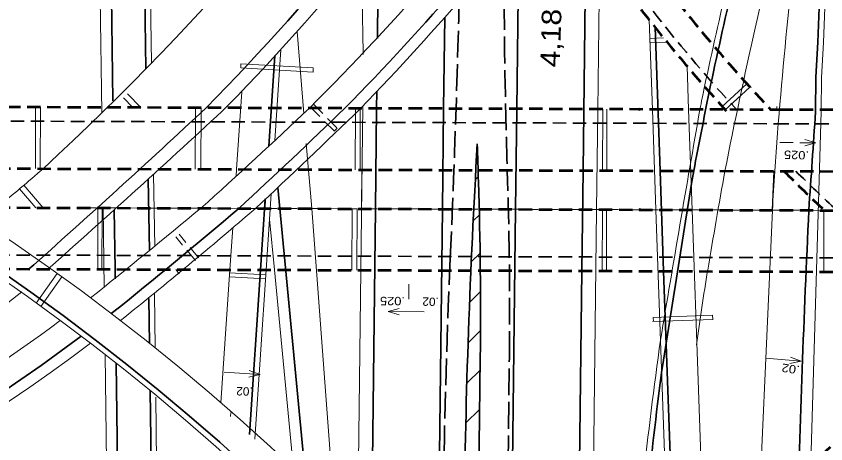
# Model space of a CAD drawing. Extents: x 2354993 to 2372084, y 6966390 to 6990057.
# Drawn here: x 2364175 to 2364756, y 6977811 to 6978118 of the extents above; entities that cross this region are included whole.
import ezdxf

# ---------------------------------------------------------------- set-up
doc = ezdxf.new("R2010")
doc.units = 0
doc.header["$LTSCALE"] = 3.2
doc.header["$PDMODE"] = 32
doc.header["$PDSIZE"] = 1.6
doc.linetypes.add('LONG_DASHED', pattern=[7.5, 6, -1.5])
doc.linetypes.add('MEDIUM_DASHED', pattern=[4.5, 3, -1.5])
for name, color, linetype, lineweight in [('11', 7, 'Continuous', 13), ('12', 7, 'Continuous', 13), ('13', 7, 'Continuous', 13), ('17', 7, 'Continuous', 13), ('19', 7, 'Continuous', 13), ('2', 7, 'Continuous', 35), ('4', 7, 'Continuous', 13), ('5', 7, 'Continuous', 35), ('6', 7, 'Continuous', 35), ('61', 7, 'Continuous', 13), ('9', 7, 'Continuous', 13)]:
    doc.layers.add(name, color=color, linetype=linetype, lineweight=lineweight)

msp = doc.modelspace()

# ---------------------------------------------------------------- linework, layer by layer
at = {"layer": '12'}
for p, q in [((2364639.282, 6978102.068), (2364629.368, 6978101.717)), ((2364629.474, 6978098.719), (2364629.368, 6978101.717)), ((2364641.658, 6978099.149), (2364629.474, 6978098.719)), ((2364336.085, 6978083.534), (2364335.918, 6978080.539)), ((2364387.788, 6978077.625), (2364335.918, 6978080.539)), ((2364387.955, 6978080.62), (2364336.085, 6978083.534)), ((2364387.955, 6978080.62), (2364387.788, 6978077.625)), ((2364254.643, 6978061.986), (2364264.214, 6978052.09)), ((2364251.767, 6978059.206), (2364258.631, 6978052.109)), ((2364303.49, 6978051.956), (2364303.342, 6978007.956)), ((2364307.49, 6978051.943), (2364307.342, 6978007.943)), ((2364595.638, 6978050.972), (2364595.489, 6978006.971)), ((2364598.637, 6978050.962), (2364598.489, 6978006.96)), ((2364405.149, 6978037.355), (2364403.014, 6978035.247)), ((2364632.9, 6978001.779), (2364633.006, 6977998.781)), ((2364177.285, 6977993.799), (2364188.905, 6977980.343)), ((2364180.313, 6977996.413), (2364194.206, 6977980.325)), ((2364233.491, 6977980.194), (2364233.343, 6977936.195)), ((2364236.49, 6977980.184), (2364236.343, 6977936.184)), ((2364595.395, 6977978.973), (2364595.246, 6977934.974)), ((2364598.394, 6977978.963), (2364598.246, 6977934.964)), ((2364754.238, 6977978.438), (2364754.09, 6977934.439)), ((2364291.836, 6977932.899), (2364289.272, 6977936.004)), ((2364294.92, 6977935.445), (2364294.473, 6977935.986)), ((2364353.954, 6977932.293), (2364327.993, 6977933.752)), ((2364353.755, 6977929.299), (2364327.795, 6977930.758)), ((2364636.538, 6977898.843), (2364636.432, 6977901.841)), ((2364328.77, 6977833.551), (2364328.601, 6977830.555))]:
    msp.add_line(p, q, dxfattribs=at)
at = {"layer": '17'}
for p, q in [((2364204.365, 6977933.072), (2364189.184, 6977911.942)), ((2364207.613, 6977930.738), (2364192.433, 6977909.608))]:
    msp.add_line(p, q, dxfattribs=at)
at = {"layer": '19', "linetype": 'MEDIUM_DASHED'}
msp.add_line((2364748.458, 6978026.804), (2364740.431, 6978024.644), dxfattribs=at)
at = {"layer": '19'}
for p, q in [((2364456.571, 6977925.613), (2364456.532, 6977914.768)), ((2364441.679, 6977905.795), (2364449.687, 6977908.023)), ((2364737.958, 6977870.263), (2364729.803, 6977868.66)), ((2364349.779, 6977860.687), (2364341.654, 6977858.935))]:
    msp.add_line(p, q, dxfattribs=at)
at = {"layer": '19', "linetype": 'MEDIUM_DASHED'}
msp.add_lwpolyline([(2364722.677, 6978027.18), (2364748.458, 6978026.804), (2364740.503, 6978029.196)], dxfattribs=at)
at = {"layer": '19'}
for points in [[(2364467.461, 6977905.634), (2364441.679, 6977905.795), (2364449.653, 6977903.47)], [(2364712.265, 6977872.416), (2364737.958, 6977870.263), (2364730.188, 6977873.197)], [(2364324.051, 6977862.367), (2364349.779, 6977860.687), (2364341.956, 6977863.478)]]:
    msp.add_lwpolyline(points, dxfattribs=at)
at = {"layer": '2'}
for p, q in [((2364535.5, 6978179.675), (2364533.978, 6978050.938)), ((2364581.463, 6978007.018), (2364583.464, 6978176.442)), ((2364481.479, 6978051.356), (2364482.253, 6978116.922)), ((2364360.38, 6978089.14), (2364356.077, 6978024.467)), ((2364533.131, 6977979.184), (2364533.978, 6978050.938)), ((2364580.614, 6977935.024), (2364581.463, 6978007.018)), ((2364353.542, 6977986.36), (2364350.178, 6977935.801)), ((2364353.105, 6977979.791), (2364353.566, 6977986.724)), ((2364529.276, 6977652.647), (2364533.131, 6977979.184)), ((2364342.329, 6977817.816), (2364350.178, 6977935.801)), ((2364576.847, 6977615.806), (2364580.614, 6977935.024))]:
    msp.add_line(p, q, dxfattribs=at)
at = {"layer": '4'}
for p, q in [((2364591.974, 6978050.253), (2364593.298, 6978162.457)), ((2364591.132, 6977978.904), (2364591.974, 6978050.253))]:
    msp.add_line(p, q, dxfattribs=at)
msp.add_lwpolyline([(2364586.065, 6977549.629), (2364586.993, 6977628.202), (2364591.132, 6977978.904)], dxfattribs=at)
at = {"layer": '4', "lineweight": 35}
for centre, radius, start, end in [((2447731.961, 6972326.416), 83180.808, 176.05509, 176.1038), ((2376431.6, 6977432.787), 11700.93, 177.32697, 178.44412)]:
    msp.add_arc(centre, radius, start, end, dxfattribs=at)
at = {"layer": '5'}
for p, q in [((2364267.888, 6978079.876), (2364263.771, 6978392.69)), ((2364433.986, 6978101.712), (2364434.867, 6978175.192)), ((2364433.997, 6978102.679), (2364433.986, 6978101.712)), ((2364433.384, 6978051.518), (2364433.533, 6978063.932)), ((2364270.487, 6977949.705), (2364269.459, 6978000.752)), ((2364504.339, 6978000.478), (2364506.337, 6978002.43)), ((2364502.851, 6977971.069), (2364506.967, 6977975.089)), ((2364501.363, 6977941.66), (2364507.57, 6977947.722)), ((2364245.809, 6977936.153), (2364245.898, 6977929.366)), ((2364648.972, 6977660.539), (2364639.273, 6977934.826)), ((2364500.194, 6977912.562), (2364507.73, 6977919.922)), ((2364270.48, 6977882.999), (2364270.055, 6977915.309)), ((2364499.216, 6977883.65), (2364507.731, 6977891.966)), ((2364246.695, 6977868.679), (2364257.91, 6977015.279)), ((2364498.238, 6977854.739), (2364507.628, 6977863.909)), ((2364280.781, 6977100.108), (2364270.924, 6977849.204)), ((2364497.402, 6977825.967), (2364507.294, 6977835.627))]:
    msp.add_line(p, q, dxfattribs=at)
at = {"layer": '5', "lineweight": 13}
for p, q in [((2364271.836, 6978083.919), (2364267.734, 6978395.661)), ((2364236.303, 6978048.324), (2364232.175, 6978361.911)), ((2364423.845, 6978091.472), (2364422.744, 6978138.5)), ((2364753.829, 6978098.812), (2364754.871, 6978123.787)), ((2364381.214, 6978047.774), (2364376.34, 6978106.754)), ((2364752.447, 6978073.796), (2364753.826, 6978098.758)), ((2364360.351, 6978028.437), (2364364.705, 6978093.867)), ((2364364.454, 6978090.1), (2364364.667, 6978093.308)), ((2364423.849, 6978090.291), (2364423.857, 6978090.987)), ((2364657.187, 6978050.764), (2364656.089, 6978081.807)), ((2364752.236, 6978048.996), (2364752.453, 6978073.982)), ((2364332.925, 6978007.856), (2364336.627, 6978063.503)), ((2364419.746, 6977748.182), (2364423.405, 6978053.282)), ((2364659.733, 6977978.756), (2364657.187, 6978050.764)), ((2364720.276, 6978050.551), (2364720.384, 6978053.024)), ((2364743.625, 6977758.845), (2364752.236, 6978048.996)), ((2364386.841, 6977979.677), (2364382.973, 6978026.488)), ((2364274.211, 6977952.737), (2364273.272, 6978004.224)), ((2364332.592, 6978002.852), (2364332.925, 6978007.856)), ((2364422.521, 6977979.556), (2364422.856, 6978007.553)), ((2364717.146, 6977978.563), (2364718.363, 6978006.556)), ((2364354.187, 6977935.787), (2364357.818, 6977990.359)), ((2364357.795, 6977990.008), (2364357.821, 6977990.399)), ((2364237.95, 6977923.17), (2364237.199, 6977980.181)), ((2364403.156, 6977764.879), (2364386.841, 6977979.677)), ((2364643.799, 6977693.64), (2364633.713, 6977978.844)), ((2364707.646, 6977760.094), (2364717.285, 6977978.562)), ((2364356.604, 6977972.114), (2364360.096, 6977935.765)), ((2364328.135, 6977935.875), (2364330.152, 6977966.192)), ((2364321.779, 6977840.341), (2364328.135, 6977935.875)), ((2364346.111, 6977814.399), (2364354.187, 6977935.787)), ((2364360.096, 6977935.765), (2364373.781, 6977793.307)), ((2364274.523, 6977879.763), (2364274.014, 6977918.463)), ((2364250.238, 6976989.323), (2364238.582, 6977875.031)), ((2364281.346, 6977361.167), (2364274.986, 6977844.567))]:
    msp.add_line(p, q, dxfattribs=at)
at = {"layer": '5', "linetype": 'MEDIUM_DASHED', "lineweight": 53}
for p, q in [((2364725.162, 6978050.535), (2364010.427, 6978052.946)), ((2365005.606, 6978049.588), (2364716.185, 6978050.564)), ((2364089.244, 6978008.678), (2364762.775, 6978006.406)), ((2363786.467, 6977981.699), (2365246.775, 6977976.776)), ((2363786.319, 6977937.7), (2365246.626, 6977932.776))]:
    msp.add_line(p, q, dxfattribs=at)
at = {"layer": '5', "linetype": 'MEDIUM_DASHED'}
for p, q in [((2364727.772, 6978040.524), (2364029.265, 6978042.88)), ((2365017.01, 6978039.548), (2364725.744, 6978040.53)), ((2363786.352, 6977947.7), (2365246.66, 6977942.776))]:
    msp.add_line(p, q, dxfattribs=at)
at = {"layer": '5', "linetype": 'MEDIUM_DASHED', "lineweight": 13}
msp.add_line((2364222.899, 6977980.23), (2364754.629, 6977978.436), dxfattribs=at)
at = {"layer": '5', "linetype": 'LONG_DASHED'}
msp.add_line((2364526.874, 6977725.884), (2364528.605, 6977872.51), dxfattribs=at)
at = {"layer": '5'}
for points in [[(2364748.237, 6978049.03), (2364748.453, 6978074.017), (2364749.833, 6978098.979), (2364750.875, 6978123.954), (2364753.046, 6978148.498), (2364754.481, 6978172.543), (2364756.316, 6978197.35), (2364758.434, 6978221.8), (2364760.985, 6978247.011), (2364763.785, 6978271.641), (2364766.943, 6978296.439), (2364770.374, 6978320.903), (2364774.178, 6978345.591), (2364778.407, 6978370.695), (2364796.946, 6978453.796)], [(2364639.273, 6977934.826), (2364636.727, 6978006.831), (2364633.086, 6978109.765)], [(2364429.624, 6977738.01), (2364432.519, 6977979.523), (2364433.384, 6978051.518)], [(2364477.172, 6977686.469), (2364480.63, 6977979.361), (2364481.479, 6978051.356)], [(2364496.142, 6977759.009), (2364495.756, 6977726.25), (2364506.002, 6977726.13), (2364507.732, 6977872.751)]]:
    msp.add_lwpolyline(points, dxfattribs=at)
at = {"layer": '5', "lineweight": 13}
for points in [[(2364633.713, 6977978.844), (2364631.167, 6978050.852), (2364628.897, 6978115.043)], [(2364680.862, 6977352.125), (2364668.863, 6977720.558), (2364659.733, 6977978.756)]]:
    msp.add_lwpolyline(points, dxfattribs=at)
at = {"layer": '5', "linetype": 'MEDIUM_DASHED', "lineweight": 53}
for centre, radius, start, end in [((2365591.415, 6978874.774), 1226.227, 157.96139, 222.27477), ((2365591.415, 6978874.774), 1202.227, 157.96139, 223.28034), ((2365591.415, 6978874.774), 1226.227, 225.07731, 226.96804), ((2365952.337, 6976500.333), 1770.947, 128.18302, 142.02993), ((2365952.338, 6976500.332), 1744.947, 127.94306, 142.26149)]:
    msp.add_arc(centre, radius, start, end, dxfattribs=at)
at = {"layer": '5', "linetype": 'MEDIUM_DASHED'}
for centre, radius, start, end in [((2365591.415, 6978874.774), 1220.227, 157.96139, 222.48424), ((2365591.415, 6978874.774), 1220.227, 225.36243, 227.27274), ((2365952.338, 6976500.332), 1748.947, 127.98178, 142.22456)]:
    msp.add_arc(centre, radius, start, end, dxfattribs=at)
at = {"layer": '5', "lineweight": 13}
for centre, radius, start, end in [((2362823.255, 6979494.499), 2021.91, 312.68984, 326.1095), ((2363008.703, 6979329.968), 1834.853, 315.90902, 326.07506), ((2363083.622, 6979356.349), 1842.854, 314.93085, 323.30202), ((2363244.672, 6976597.082), 1645.014, 38.12295, 103.3303), ((2363062.003, 6979373.816), 1896.709, 315.80261, 322.95759), ((2368298.716, 6977752.87), 3588.778, 172.43843, 175.94649), ((2363244.672, 6976597.082), 1619.014, 38.12295, 103.3303), ((2368172.363, 6977322.346), 3582.03, 165.52996, 167.99765), ((2368799.967, 6977188.312), 4197.305, 165.90092, 168.75683), ((2367491.502, 6977482.494), 2882.789, 168.29699, 168.63166), ((2359454.929, 6983291.9), 7153.737, 311.52024, 312.92114), ((2361503.345, 6981100.379), 4195.154, 311.94226, 313.38798), ((2361441.841, 6981104.619), 4266.326, 312.90909, 314.30611), ((2381410.768, 6975102.784), 17003, 170.0157, 170.58074), ((2363127.192, 6979233.99), 1625.022, 309.51957, 311.04051), ((2371644.782, 6976761.528), 7072.044, 169.8593, 170.44507), ((2367582.002, 6977825.766), 2868.789, 176.38689, 176.9469), ((2361053.508, 6981904.182), 5097.73, 308.51788, 309.66398), ((2361981.19, 6980728.955), 3626.643, 308.71864, 310.70824), ((2367491.502, 6977482.494), 2856.789, 170.87724, 171.96261), ((2363127.192, 6979233.99), 1683.022, 290.12282, 308.67239), ((2363217.727, 6979240.251), 1666, 287.12386, 306.40449), ((2363217.727, 6979240.251), 1692, 268.21361, 306.66787), ((2367491.502, 6977482.494), 2882.789, 171.96478, 176.02877)]:
    msp.add_arc(centre, radius, start, end, dxfattribs=at)
at = {"layer": '5'}
for centre, radius, start, end in [((2363014.544, 6979325.529), 1817.476, 315.51277, 326.29202), ((2363069.263, 6979367.953), 1879.359, 315.5386, 323.05986), ((2363244.672, 6976597.082), 1623.014, 38.12295, 103.3303), ((2368154.706, 6977326.865), 3559.803, 165.52972, 168.05788), ((2377217.033, 6975580.088), 12788.526, 168.80268, 169.06162), ((2359575.641, 6983131.748), 6944.748, 311.568, 312.99093), ((2361460.638, 6981103.363), 4244.476, 312.61669, 314.02824), ((2370213.297, 6977689.532), 5717.578, 176.62485, 179.32419), ((2370233.103, 6978181.658), 5729.578, 181.55533, 181.82765), ((2379301.639, 6975604.682), 14836.529, 170.68267, 171.24852), ((2361643.141, 6977906.558), 2864.789, 359.32384, 1.84755), ((2361795.315, 6980964.189), 3918.403, 308.65893, 310.39274), ((2363217.727, 6979240.251), 1684, 268.21361, 306.58945), ((2367491.502, 6977482.494), 2878.789, 172.42387, 176.02877)]:
    msp.add_arc(centre, radius, start, end, dxfattribs=at)
at = {"layer": '5', "linetype": 'LONG_DASHED'}
for centre, radius, start, end in [((2355201.239, 6978357.07), 9294.189, 357.45391, 359.3238), ((2370414.262, 6978177.512), 5889.645, 179.32374, 181.73104), ((2361643.141, 6977906.564), 2885.664, 359.32384, 1.84755), ((2370213.296, 6977689.531), 5732.703, 177.45392, 179.32419)]:
    msp.add_arc(centre, radius, start, end, dxfattribs=at)
at = {"layer": '6'}
for p, q in [((2364244.21, 6978056.977), (2364240.055, 6978371.067)), ((2364362.469, 6977994.721), (2364363.907, 6977979.755)), ((2364245.809, 6977936.153), (2364245.245, 6977978.819)), ((2364363.907, 6977979.755), (2364382.624, 6977784.897))]:
    msp.add_line(p, q, dxfattribs=at)
at = {"layer": '61'}
for p, q in [((2364699.004, 6978069.192), (2364680.9, 6978052.761)), ((2364701.188, 6978066.786), (2364683.084, 6978050.354)), ((2364188.651, 6978008.343), (2364188.8, 6978052.536)), ((2364192.151, 6978008.331), (2364192.3, 6978052.524)), ((2364418.05, 6978007.569), (2364418.198, 6978051.596)), ((2364421.55, 6978007.557), (2364421.698, 6978051.585)), ((2364415.702, 6977935.578), (2364415.85, 6977979.635)), ((2364419.202, 6977935.566), (2364419.35, 6977979.623)), ((2364674.708, 6977900.191), (2364631.185, 6977898.654)), ((2364674.101, 6977903.172), (2364631.73, 6977901.675)), ((2364631.816, 6977901.678), (2364631.922, 6977898.68)), ((2364674.349, 6977903.181), (2364674.455, 6977900.182))]:
    msp.add_line(p, q, dxfattribs=at)
at = {"layer": '61', "linetype": 'MEDIUM_DASHED'}
for p, q in [((2364385.981, 6978052.502), (2364403.014, 6978035.247)), ((2364388.116, 6978054.61), (2364405.149, 6978037.355)), ((2364303.414, 6977942.443), (2364289.423, 6977959.421)), ((2364305.729, 6977944.351), (2364291.738, 6977961.329))]:
    msp.add_line(p, q, dxfattribs=at)
at = {"layer": '9'}
for p in [(2364621.775, 6978050.883), (2364622.266, 6977978.883)]:
    msp.add_point(p, dxfattribs=at)

# ---------------------------------------------------------------- texts
at = {"layer": '11', "width": 1.15}
msp.add_text('.025', height=6, rotation=178.117, dxfattribs=at).set_placement((2364743.64, 6978020.808))
at = {"layer": '13', "width": 1.15}
msp.add_text('4,184', height=14, rotation=88.164, dxfattribs=at).set_placement((2364564.684, 6978080.867))
at = {"layer": '19'}
for s, height, rotation, width, p in [('.025', 6, 179.794, 1.15, (2364453.759, 6977916.375)), ('.02', 5.999, 178.287, 1.05, (2364478.068, 6977915.719)), ('.02', 6, 171.703, 1.15, (2364737.182, 6977866.778)), ('.02', 6, 178.438, 1.05, (2364344.563, 6977851.464))]:
    msp.add_text(s, height=height, rotation=rotation, dxfattribs=dict(at, width=width)).set_placement(p)

doc.saveas('drawing.dxf')
